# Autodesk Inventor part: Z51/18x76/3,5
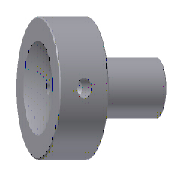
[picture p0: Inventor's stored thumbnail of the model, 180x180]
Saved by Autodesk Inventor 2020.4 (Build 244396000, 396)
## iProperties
Created: 2019-01
Part Number: Z51/18x76/3,5
Material: 1.2826
Description: Sprue Bushing
Document SubType Name: Modeling
Designer: mel
Standard Revision: 1
Manufacturer: HASCO
Language: fr-FR
Size Designation: 18x76/3,5
Categories: <MemberInstance><Categories><Category DisplayName="Moule" InternalName="349578f2-f4d4-4954-8c09-8e99297a61c0" Mnemonic="MOLD"><Category DisplayName="Canal d'inj
Density: 7.82 g/cm^3
Appearance: Par défaut
IsCustomPart: 1
Author: mel
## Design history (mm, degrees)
sketch "Sketch1"
  geometry: L1 (0, -27.2)-(0, 23.2) reference; L2 (1.75, 18)-(19, 18); L3 (19, 18)-(19, 0); L4 (19, 0)-(12, 0); L5 (9, -3)-(9, -76); L6 (9, -76)-(4.211, -76); L7 (4.211, -76)-(1.75, 18); A1 r 3 centre (12, -3) between (12, 0) and (9, -3); 2 further points
  constraints: 12 end point, 3 parallel, 2 perpendicular, 2 point on circle, 2 point on line, 2 tangent, 1 centre point
  dimensions: "d0" = 18 diameter of L5 L1 (= D); "d3" = 38 diameter of L3 L1 (= d1); "d6" = 1.5 deg angle of L7 L1 (= 0.5 x Taper); "d7" = 18 distance between parallel lines of L4 L2 (= K_); "d8" = 76 distance between parallel lines of L4 L6 (= L); "d9" = 3 radius of A1 (= R3); "d62" = 3.5 diameter of point (1.75, 18) L1 (= d_); "d63" = 0 distance from line of point (1.75, 18) L2 (computed from Rd)
revolve "Revolution1" sketch "Sketch1" stored, may be unused: angle "d10" = 90 deg
sketch "Sketch2"
  geometry: L1 (0, -32.79)-(0, 56.739) reference; L2 (4.211, -76)-(1.75, 18) reference; L3 (-19, 18)-(19, 18) reference; L4 (0, 48.901)-(0, 17.901); A1 r 15.5 centre (0, 33.401) between (0, 17.901) and (0, 48.901); 2 further points
  constraints: 3 point on circle, 3 point on line, 2 end point, 1 centre point, 1 midpoint
  dimensions: "d64" = 0 distance from line of point (1.75, 18) L3 (computed from Rd); "d67" = 15.5 radius of A1 (= Rk)
revolve "Revolution2" sketch "Sketch2" stored, may be unused: angle "d13" = 90 deg
workplane "Work Plane1"
sketch "Sketch3"
  geometry: 2 further points
  constraints: 1 vertical alignment
  dimensions: "d43" = 9 distance of point (0, -9) point (0, 0) (= 0.5 x K_)
hole "Hole1" sketch "Sketch3" at (0, 0) diameter "d15" = 4 (= pd1); stored, may be unused: countersink angle "d19" = 90 deg, drill point angle "d21" = 118 deg; dims "d16" = 6, "d17" = 4, "d18" = 2, "d20" = 6 (= pl1)
chamfer "Chamfer1" distance "d22" = 0.3; stored, may be unused: second distance "d23" = 2, angle "d24" = 45 deg
sketch "Sketch4"
  geometry: L1 (0, -30.4)-(0, 42.4) reference; L2 (0, 36)-(19.5, 36); L3 (19.5, 36)-(19.5, 0); L4 (9, -76)-(0, -76); L5 (0, -76)-(0, 36); L6 (9, -3)-(9, -76); L7 (12, 0)-(19.5, 0); L8 (12, 0)-(9, -3); 2 further points
  constraints: 14 end point, 4 point on line, 2 horizontal, 2 parallel, 1 perpendicular, 1 vertical
  dimensions: "d56" = 3 distance of L7.start point (9, 0) (= R3_CS); "d57" = 3 distance of L6.start point (9, 0) (= d56); "d58" = 39 diameter of L3 L1 (= d1_CS); "d59" = 36 distance between parallel lines of L7 L2 (= K_CS); "d60" = 18 diameter of L6 L1 (= D_CS); "d61" = 76 distance between parallel lines of L7 L4 (= L_CS)
feature "RevolutionSrf1" sketch "Sketch4" dims angle "d33" = 90 deg
body "Solid1"
body "Srf1"
other parameters: "L" = 76 [user parameter; used in 1 equation term], "d1" = 38 [user parameter; used in 1 equation term], "d_" = 3.5 [user parameter; used in 1 equation term], "D" = 18 [user parameter; used in 1 equation term], "K_" = 18 [user parameter; used in 2 equation terms], "R" = 0 [user parameter], "Taper" = 3 deg [user parameter; used in 1 equation term], "Rd" = 0 [user parameter; used in 2 equation terms], "R3" = 3 [user parameter; used in 1 equation term], "pd1" = 4 [user parameter; used in 1 equation term], "d1_CS" = 39 [user parameter; used in 1 equation term], "K_CS" = 36 [user parameter; used in 1 equation term], "d44" = 0, "d45" = 0, "d46" = 0, "L_CS" = 76 [user parameter; used in 1 equation term], "D_CS" = 18 [user parameter; used in 1 equation term], "pl1" = 6 [user parameter; used in 1 equation term], "R3_CS" = 3 [user parameter; used in 1 equation term], "Rk" = 15.5 [user parameter; used in 1 equation term]
